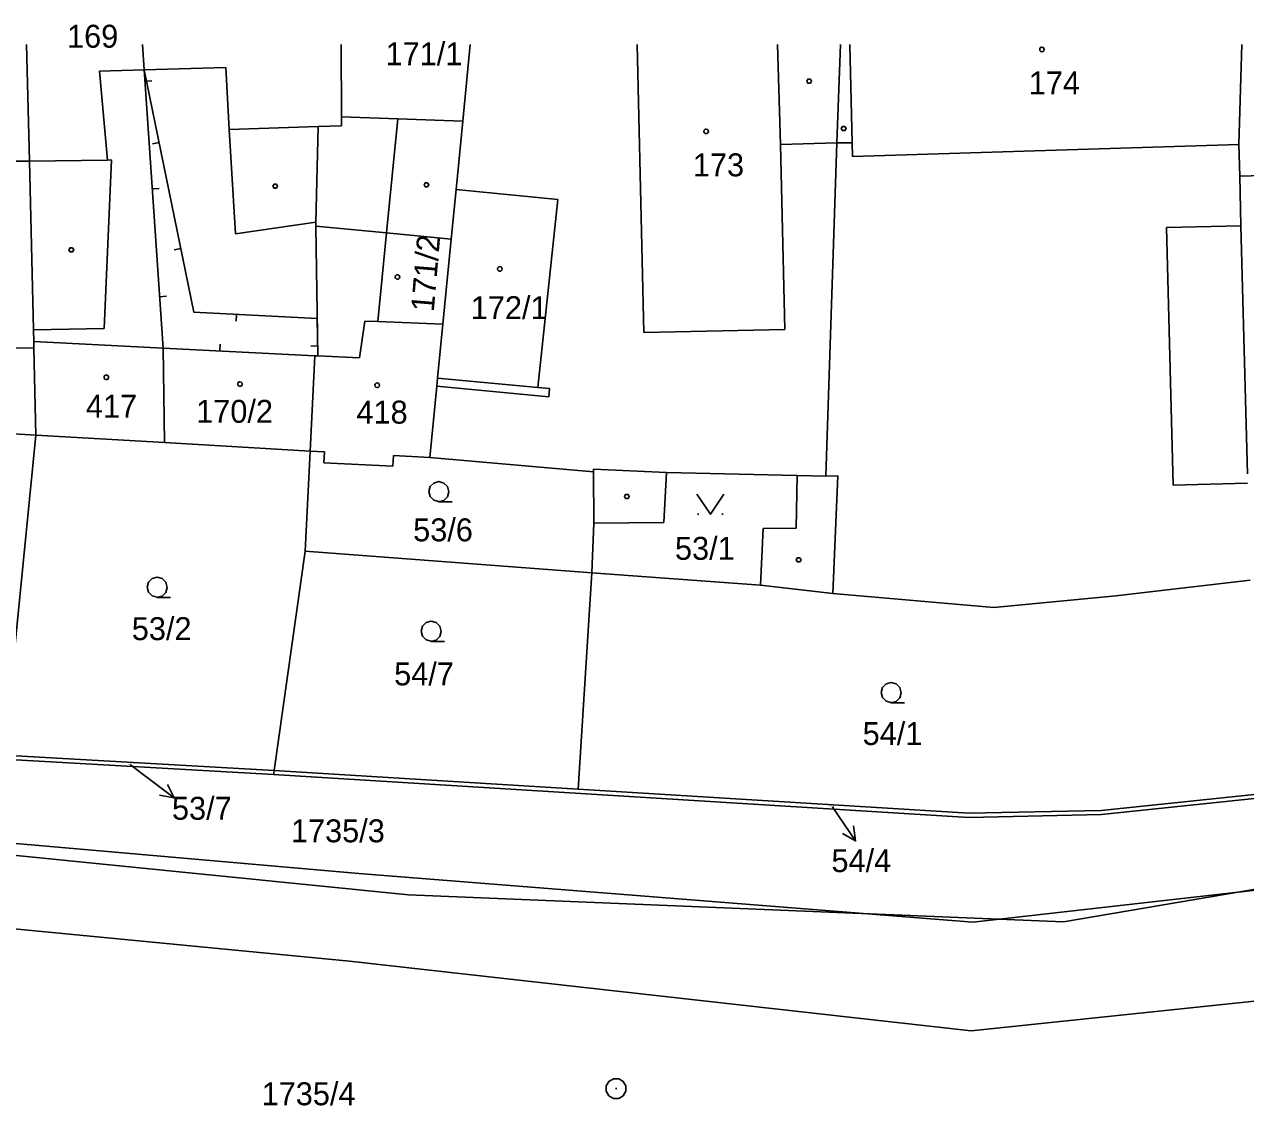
# Model space of a CAD drawing. Extents: x -777309 to -774195, y -1144706 to -1143600.
# Drawn here: x -774889 to -774798.5, y -1144278.6 to -1144198.5 of the extents above; entities that cross this region are included whole.
import ezdxf

# ---------------------------------------------------------------- set-up
doc = ezdxf.new("R2010")
doc.units = 0
for name, color, linetype in [('1', 7, 'Continuous'), ('11', 7, 'Continuous'), ('12', 7, 'Continuous'), ('13', 7, 'Continuous'), ('2', 7, 'Continuous'), ('3', 7, 'Continuous'), ('4', 7, 'Continuous'), ('5', 7, 'Continuous'), ('7', 7, 'Continuous'), ('8', 7, 'Continuous')]:
    doc.layers.add(name, color=color, linetype=linetype)

msp = doc.modelspace()

# ---------------------------------------------------------------- linework, layer by layer
at = {"layer": '1'}
for p, q in [((-774888.59, -1144208.64), (-774888.8, -1144200)), ((-774880.207, -1144200), (-774880.08, -1144201.87)), ((-774865.48, -1144205.35), (-774865.502, -1144200)), ((-774855.935, -1144200), (-774856.49, -1144205.68)), ((-774843.569, -1144200), (-774843.07, -1144221.34)), ((-774828.514, -1144200), (-774828.78, -1144207.29)), ((-774799, -1144207.4), (-774798.795, -1144200)), ((-774880.08, -1144201.87), (-774878.67, -1144222.48)), ((-774865.47, -1144206.03), (-774865.48, -1144205.35)), ((-774867.37, -1144213.16), (-774867.21, -1144206.06)), ((-774867.21, -1144206.06), (-774865.47, -1144206.03)), ((-774856.99, -1144210.73), (-774856.49, -1144205.68)), ((-774832.95, -1144207.39), (-774828.78, -1144207.29)), ((-774832.63, -1144221.1), (-774832.95, -1144207.39)), ((-774828.78, -1144207.29), (-774829.59, -1144231.98)), ((-774798.94, -1144209.74), (-774799, -1144207.4)), ((-774888.29, -1144221.14), (-774888.59, -1144208.64)), ((-774798.85, -1144213.42), (-774798.94, -1144209.74)), ((-774856.99, -1144210.73), (-774857.35, -1144214.42)), ((-774867.36, -1144213.44), (-774867.37, -1144213.16)), ((-774862.13, -1144213.95), (-774867.36, -1144213.44)), ((-774867.23, -1144223.06), (-774867.36, -1144213.44)), ((-774798.37, -1144231.8), (-774798.85, -1144213.42)), ((-774862.13, -1144213.95), (-774857.35, -1144214.42)), ((-774857.35, -1144214.42), (-774857.97, -1144220.7)), ((-774863.74, -1144220.49), (-774864.15, -1144223.21)), ((-774862.77, -1144220.52), (-774863.74, -1144220.49)), ((-774862.77, -1144220.52), (-774857.97, -1144220.7)), ((-774857.97, -1144220.7), (-774858.36, -1144224.71)), ((-774888.27, -1144221.99), (-774888.29, -1144221.14)), ((-774843.07, -1144221.34), (-774832.63, -1144221.1)), ((-774888.26, -1144222.49), (-774888.27, -1144221.99)), ((-774878.67, -1144222.48), (-774888.27, -1144221.99)), ((-774888.1, -1144228.93), (-774888.26, -1144222.49)), ((-774867.45, -1144223.05), (-774878.67, -1144222.48)), ((-774878.67, -1144222.48), (-774878.59, -1144229.48)), ((-774867.78, -1144230.11), (-774867.45, -1144223.05)), ((-774867.45, -1144223.05), (-774867.23, -1144223.06)), ((-774864.15, -1144223.21), (-774867.23, -1144223.06)), ((-774858.42, -1144225.31), (-774858.94, -1144230.59)), ((-774858.36, -1144224.71), (-774858.42, -1144225.31)), ((-774888.1, -1144228.93), (-774896.67, -1144228.43)), ((-774890.45, -1144252.65), (-774888.1, -1144228.93)), ((-774878.59, -1144229.48), (-774888.1, -1144228.93)), ((-774867.78, -1144230.11), (-774878.59, -1144229.48)), ((-774868.17, -1144237.53), (-774867.78, -1144230.11)), ((-774866.73, -1144230.17), (-774867.78, -1144230.11)), ((-774866.78, -1144230.99), (-774866.73, -1144230.17)), ((-774861.66, -1144231.24), (-774866.78, -1144230.99)), ((-774861.61, -1144230.45), (-774861.66, -1144231.24)), ((-774858.94, -1144230.59), (-774861.61, -1144230.45)), ((-774858.94, -1144230.59), (-774846.81, -1144231.65)), ((-774846.81, -1144231.65), (-774846.78, -1144235.45)), ((-774841.6, -1144235.41), (-774841.4, -1144231.69)), ((-774841.4, -1144231.69), (-774831.71, -1144231.93)), ((-774831.71, -1144231.93), (-774831.8, -1144235.82)), ((-774829.59, -1144231.98), (-774828.72, -1144231.96)), ((-774828.72, -1144231.96), (-774829.09, -1144240.66)), ((-774846.94, -1144239.14), (-774846.78, -1144235.45)), ((-774846.78, -1144235.45), (-774841.6, -1144235.41)), ((-774834.25, -1144235.84), (-774834.43, -1144240.06)), ((-774831.8, -1144235.82), (-774834.25, -1144235.84)), ((-774868.17, -1144237.53), (-774870.47, -1144253.78)), ((-774846.94, -1144239.14), (-774868.17, -1144237.53)), ((-774846.94, -1144239.14), (-774847.93, -1144255.17)), ((-774834.43, -1144240.06), (-774846.94, -1144239.14)), ((-774808.13, -1144240.85), (-774798.17, -1144239.67)), ((-774829.09, -1144240.66), (-774834.43, -1144240.06)), ((-774829.09, -1144240.66), (-774817.16, -1144241.7)), ((-774817.16, -1144241.7), (-774808.13, -1144240.85)), ((-774890.45, -1144252.65), (-774870.47, -1144253.78)), ((-774890.48, -1144252.95), (-774870.51, -1144254.08)), ((-774870.47, -1144253.78), (-774870.51, -1144254.08)), ((-774819, -1144257.25), (-774870.51, -1144254.08)), ((-774870.47, -1144253.78), (-774847.93, -1144255.17)), ((-774847.93, -1144255.17), (-774819, -1144256.95)), ((-774809.2, -1144256.75), (-774790.9, -1144254.82)), ((-774790.85, -1144255.12), (-774809.17, -1144257.05)), ((-774819, -1144256.95), (-774809.2, -1144256.75)), ((-774809.17, -1144257.05), (-774819, -1144257.25)), ((-774864.19, -1144261.41), (-774902.17, -1144258.08)), ((-774818.72, -1144265.01), (-774773.33, -1144259.89)), ((-774864.19, -1144261.41), (-774818.72, -1144265.01)), ((-774864.87, -1144267.9), (-774902.82, -1144264.25)), ((-774818.84, -1144273.07), (-774864.87, -1144267.9)), ((-774782.45, -1144269.27), (-774818.84, -1144273.07))]:
    msp.add_line(p, q, dxfattribs=at)
at = {"layer": '11'}
msp.add_lwpolyline([(-774645.079, -1144200), (-774645.5, -1144200.5), (-774681.5, -1144228), (-774709.5, -1144242), (-774744.5, -1144253.5), (-774812, -1144265), (-774860.5, -1144263), (-774969.04, -1144252.1), (-774980.31, -1144239.8), (-774996.3, -1144228.96), (-775000, -1144226.45), (-775000, -1144224.76), (-775020.31, -1144224.68)], dxfattribs=at)
at = {"layer": '12'}
for p, q in [((-774888.59, -1144208.64), (-774888.8, -1144200)), ((-774888.59, -1144208.64), (-774888.8, -1144200)), ((-774880.207, -1144200), (-774880.08, -1144201.87)), ((-774880.207, -1144200), (-774880.08, -1144201.87)), ((-774865.48, -1144205.35), (-774865.502, -1144200)), ((-774865.48, -1144205.35), (-774865.502, -1144200)), ((-774855.935, -1144200), (-774856.49, -1144205.68)), ((-774843.569, -1144200), (-774843.07, -1144221.34)), ((-774832.95, -1144207.39), (-774833.173, -1144200)), ((-774827.65, -1144207.27), (-774827.824, -1144200)), ((-774799, -1144207.4), (-774798.795, -1144200)), ((-774799, -1144207.4), (-774798.795, -1144200)), ((-774883.39, -1144201.96), (-774880.08, -1144201.87)), ((-774882.8, -1144208.55), (-774883.39, -1144201.96)), ((-774880.08, -1144201.87), (-774874.04, -1144201.7)), ((-774874.04, -1144201.7), (-774873.78, -1144206.3)), ((-774865.47, -1144206.03), (-774865.48, -1144205.35)), ((-774865.48, -1144205.35), (-774861.3, -1144205.5)), ((-774861.3, -1144205.5), (-774856.49, -1144205.68)), ((-774873.78, -1144206.3), (-774867.21, -1144206.06)), ((-774867.21, -1144206.06), (-774865.47, -1144206.03)), ((-774832.63, -1144221.1), (-774832.95, -1144207.39)), ((-774827.65, -1144207.27), (-774827.63, -1144208.28)), ((-774827.63, -1144208.28), (-774799, -1144207.4)), ((-774798.94, -1144209.74), (-774799, -1144207.4)), ((-774892.65, -1144208.65), (-774888.59, -1144208.64)), ((-774888.59, -1144208.64), (-774882.8, -1144208.55)), ((-774758.75, -1144208.58), (-774798.94, -1144209.74)), ((-774856.99, -1144210.73), (-774857.35, -1144214.42)), ((-774856.99, -1144210.73), (-774849.45, -1144211.47)), ((-774849.45, -1144211.47), (-774850.94, -1144225.41)), ((-774862.13, -1144213.95), (-774862.77, -1144220.52)), ((-774862.13, -1144213.95), (-774857.35, -1144214.42)), ((-774857.35, -1144214.42), (-774857.97, -1144220.7)), ((-774857.35, -1144214.42), (-774857.97, -1144220.7)), ((-774863.74, -1144220.49), (-774864.15, -1144223.21)), ((-774862.77, -1144220.52), (-774863.74, -1144220.49)), ((-774862.77, -1144220.52), (-774857.97, -1144220.7)), ((-774862.77, -1144220.52), (-774857.97, -1144220.7)), ((-774857.97, -1144220.7), (-774858.36, -1144224.71)), ((-774857.97, -1144220.7), (-774858.36, -1144224.71)), ((-774843.07, -1144221.34), (-774832.63, -1144221.1)), ((-774888.26, -1144222.49), (-774888.27, -1144221.99)), ((-774878.67, -1144222.48), (-774888.27, -1144221.99)), ((-774888.1, -1144228.93), (-774888.26, -1144222.49)), ((-774878.67, -1144222.48), (-774878.59, -1144229.48)), ((-774867.45, -1144223.05), (-774878.67, -1144222.48)), ((-774878.67, -1144222.48), (-774878.59, -1144229.48)), ((-774867.78, -1144230.11), (-774867.45, -1144223.05)), ((-774867.78, -1144230.11), (-774867.45, -1144223.05)), ((-774867.45, -1144223.05), (-774867.23, -1144223.06)), ((-774864.15, -1144223.21), (-774867.23, -1144223.06)), ((-774858.42, -1144225.31), (-774858.94, -1144230.59)), ((-774858.36, -1144224.71), (-774858.42, -1144225.31)), ((-774858.36, -1144224.71), (-774850.94, -1144225.41)), ((-774878.59, -1144229.48), (-774888.1, -1144228.93)), ((-774867.78, -1144230.11), (-774878.59, -1144229.48)), ((-774866.73, -1144230.17), (-774867.78, -1144230.11)), ((-774866.78, -1144230.99), (-774866.73, -1144230.17)), ((-774861.66, -1144231.24), (-774866.78, -1144230.99)), ((-774861.61, -1144230.45), (-774861.66, -1144231.24)), ((-774858.94, -1144230.59), (-774861.61, -1144230.45))]:
    msp.add_line(p, q, dxfattribs=at)
at = {"layer": '13'}
for p, q in [((-774880.022, -1144202.716), (-774879.523, -1144202.682)), ((-774878.976, -1144207.258), (-774879.466, -1144207.358)), ((-774879.476, -1144210.698), (-774878.977, -1144210.664)), ((-774877.37, -1144215.095), (-774877.86, -1144215.195)), ((-774878.93, -1144218.679), (-774878.431, -1144218.645)), ((-774873.237, -1144219.993), (-774873.263, -1144220.492)), ((-774874.485, -1144222.693), (-774874.46, -1144222.193)), ((-774867.241, -1144222.325), (-774867.741, -1144222.332))]:
    msp.add_line(p, q, dxfattribs=at)
msp.add_lwpolyline([(-774880.08, -1144201.87), (-774876.4, -1144219.83), (-774867.27, -1144220.3), (-774867.23, -1144223.06), (-774867.45, -1144223.05), (-774878.67, -1144222.48)], close=True, dxfattribs=at)
at = {"layer": '3'}
for p, q in [((-774839.1, -1144234.8), (-774839, -1144234.8)), ((-774837.3, -1144234.8), (-774837.2, -1144234.8))]:
    msp.add_line(p, q, dxfattribs=at)
for points in [[(-774858.25, -1144233.86), (-774858.63, -1144233.76), (-774858.9, -1144233.49), (-774859, -1144233.12), (-774858.9, -1144232.75), (-774858.63, -1144232.48), (-774858.26, -1144232.38), (-774857.89, -1144232.48), (-774857.62, -1144232.75), (-774857.52, -1144233.13), (-774857.62, -1144233.51), (-774857.89, -1144233.78), (-774858.27, -1144233.88), (-774857.27, -1144233.88)], [(-774839.15, -1144233.3), (-774838.15, -1144234.8), (-774837.15, -1144233.3)], [(-774879.11, -1144240.94), (-774879.49, -1144240.84), (-774879.76, -1144240.57), (-774879.86, -1144240.2), (-774879.76, -1144239.83), (-774879.49, -1144239.56), (-774879.12, -1144239.46), (-774878.75, -1144239.56), (-774878.48, -1144239.83), (-774878.38, -1144240.21), (-774878.48, -1144240.59), (-774878.75, -1144240.86), (-774879.13, -1144240.96), (-774878.13, -1144240.96)], [(-774858.82, -1144244.2), (-774859.2, -1144244.1), (-774859.47, -1144243.83), (-774859.57, -1144243.46), (-774859.47, -1144243.09), (-774859.2, -1144242.82), (-774858.83, -1144242.72), (-774858.46, -1144242.82), (-774858.19, -1144243.09), (-774858.09, -1144243.47), (-774858.19, -1144243.85), (-774858.46, -1144244.12), (-774858.84, -1144244.22), (-774857.84, -1144244.22)], [(-774824.76, -1144248.75), (-774825.14, -1144248.65), (-774825.41, -1144248.38), (-774825.51, -1144248.01), (-774825.41, -1144247.64), (-774825.14, -1144247.37), (-774824.77, -1144247.27), (-774824.4, -1144247.37), (-774824.13, -1144247.64), (-774824.03, -1144248.02), (-774824.13, -1144248.4), (-774824.4, -1144248.67), (-774824.78, -1144248.77), (-774823.78, -1144248.77)]]:
    msp.add_lwpolyline(points, dxfattribs=at)
at = {"layer": '4'}
for p, q in [((-774832.95, -1144207.39), (-774833.173, -1144200)), ((-774827.65, -1144207.27), (-774827.824, -1144200)), ((-774883.39, -1144201.96), (-774880.08, -1144201.87)), ((-774882.8, -1144208.55), (-774883.39, -1144201.96)), ((-774880.08, -1144201.87), (-774874.04, -1144201.7)), ((-774874.04, -1144201.7), (-774873.78, -1144206.3)), ((-774865.48, -1144205.35), (-774861.3, -1144205.5)), ((-774861.3, -1144205.5), (-774862.13, -1144213.95)), ((-774861.3, -1144205.5), (-774856.49, -1144205.68)), ((-774873.78, -1144206.3), (-774867.21, -1144206.06)), ((-774873.78, -1144206.3), (-774873.33, -1144214.02)), ((-774828.78, -1144207.29), (-774827.65, -1144207.27)), ((-774827.65, -1144207.27), (-774827.63, -1144208.28)), ((-774827.63, -1144208.28), (-774799, -1144207.4)), ((-774892.65, -1144208.65), (-774888.59, -1144208.64)), ((-774888.59, -1144208.64), (-774882.8, -1144208.55)), ((-774883.06, -1144221.03), (-774882.5, -1144208.54)), ((-774882.5, -1144208.54), (-774882.8, -1144208.55)), ((-774758.75, -1144208.58), (-774798.94, -1144209.74)), ((-774856.99, -1144210.73), (-774849.45, -1144211.47)), ((-774849.45, -1144211.47), (-774850.94, -1144225.41)), ((-774873.33, -1144214.02), (-774867.37, -1144213.16)), ((-774798.85, -1144213.42), (-774804.37, -1144213.56)), ((-774804.37, -1144213.56), (-774803.88, -1144232.63)), ((-774862.13, -1144213.95), (-774862.77, -1144220.52)), ((-774888.29, -1144221.14), (-774883.06, -1144221.03)), ((-774892.63, -1144222.47), (-774888.26, -1144222.49)), ((-774850.12, -1144226.09), (-774858.42, -1144225.31)), ((-774858.36, -1144224.71), (-774850.94, -1144225.41)), ((-774850.94, -1144225.41), (-774850.06, -1144225.49)), ((-774850.06, -1144225.49), (-774850.12, -1144226.09)), ((-774846.81, -1144231.65), (-774846.81, -1144231.45)), ((-774846.81, -1144231.45), (-774841.4, -1144231.69)), ((-774831.71, -1144231.93), (-774829.59, -1144231.98)), ((-774803.88, -1144232.63), (-774798.36, -1144232.49))]:
    msp.add_line(p, q, dxfattribs=at)
at = {"layer": '5'}
for points in [[(-774813.59, -1144200.19), (-774813.49, -1144200.21), (-774813.44, -1144200.3), (-774813.42, -1144200.36), (-774813.44, -1144200.45), (-774813.52, -1144200.52), (-774813.59, -1144200.53), (-774813.68, -1144200.5), (-774813.74, -1144200.44), (-774813.76, -1144200.36), (-774813.74, -1144200.27), (-774813.66, -1144200.2)], [(-774830.74, -1144202.56), (-774830.65, -1144202.71), (-774830.74, -1144202.86), (-774830.92, -1144202.86), (-774831.01, -1144202.71), (-774830.92, -1144202.56)], [(-774838.47, -1144206.26), (-774838.37, -1144206.28), (-774838.32, -1144206.37), (-774838.3, -1144206.43), (-774838.32, -1144206.52), (-774838.4, -1144206.59), (-774838.47, -1144206.6), (-774838.56, -1144206.57), (-774838.62, -1144206.51), (-774838.64, -1144206.43), (-774838.62, -1144206.34), (-774838.54, -1144206.27)], [(-774828.19, -1144206.07), (-774828.1, -1144206.22), (-774828.19, -1144206.37), (-774828.37, -1144206.37), (-774828.46, -1144206.22), (-774828.37, -1144206.07)], [(-774870.29, -1144210.34), (-774870.2, -1144210.49), (-774870.29, -1144210.64), (-774870.47, -1144210.64), (-774870.56, -1144210.49), (-774870.47, -1144210.34)], [(-774859.09, -1144210.23), (-774859, -1144210.38), (-774859.09, -1144210.53), (-774859.27, -1144210.53), (-774859.36, -1144210.38), (-774859.27, -1144210.23)], [(-774885.39, -1144215.06), (-774885.3, -1144215.21), (-774885.39, -1144215.36), (-774885.57, -1144215.36), (-774885.66, -1144215.21), (-774885.57, -1144215.06)], [(-774853.74, -1144216.45), (-774853.64, -1144216.47), (-774853.59, -1144216.56), (-774853.57, -1144216.62), (-774853.59, -1144216.71), (-774853.67, -1144216.78), (-774853.74, -1144216.79), (-774853.83, -1144216.76), (-774853.89, -1144216.7), (-774853.91, -1144216.62), (-774853.89, -1144216.53), (-774853.81, -1144216.46)], [(-774861.33, -1144217.05), (-774861.23, -1144217.07), (-774861.18, -1144217.16), (-774861.16, -1144217.22), (-774861.18, -1144217.31), (-774861.26, -1144217.38), (-774861.33, -1144217.39), (-774861.42, -1144217.36), (-774861.48, -1144217.3), (-774861.5, -1144217.22), (-774861.48, -1144217.13), (-774861.4, -1144217.06)], [(-774882.89, -1144224.48), (-774882.79, -1144224.5), (-774882.74, -1144224.59), (-774882.72, -1144224.65), (-774882.74, -1144224.74), (-774882.82, -1144224.81), (-774882.89, -1144224.82), (-774882.98, -1144224.79), (-774883.04, -1144224.73), (-774883.06, -1144224.65), (-774883.04, -1144224.56), (-774882.96, -1144224.49)], [(-774872.99, -1144224.98), (-774872.89, -1144225), (-774872.84, -1144225.09), (-774872.82, -1144225.15), (-774872.84, -1144225.24), (-774872.92, -1144225.31), (-774872.99, -1144225.32), (-774873.08, -1144225.29), (-774873.14, -1144225.23), (-774873.16, -1144225.15), (-774873.14, -1144225.06), (-774873.06, -1144224.99)], [(-774862.83, -1144225.07), (-774862.73, -1144225.09), (-774862.68, -1144225.18), (-774862.66, -1144225.24), (-774862.68, -1144225.33), (-774862.76, -1144225.4), (-774862.83, -1144225.41), (-774862.92, -1144225.38), (-774862.98, -1144225.32), (-774863, -1144225.24), (-774862.98, -1144225.15), (-774862.9, -1144225.08)], [(-774844.25, -1144233.32), (-774844.16, -1144233.47), (-774844.25, -1144233.62), (-774844.43, -1144233.62), (-774844.52, -1144233.47), (-774844.43, -1144233.32)], [(-774831.52, -1144238.02), (-774831.43, -1144238.17), (-774831.52, -1144238.32), (-774831.7, -1144238.32), (-774831.79, -1144238.17), (-774831.7, -1144238.02)]]:
    msp.add_lwpolyline(points, close=True, dxfattribs=at)
at = {"layer": '7'}
for p, q in [((-774881.09, -1144253.37), (-774880.25, -1144254)), ((-774877.859, -1144255.812), (-774880.25, -1144254)), ((-774829.11, -1144256.48), (-774829.09, -1144256.52)), ((-774827.398, -1144258.997), (-774829.09, -1144256.52))]:
    msp.add_line(p, q, dxfattribs=at)
for points in [[(-774878.354, -1144254.809), (-774877.859, -1144255.812), (-774878.958, -1144255.606)], [(-774827.549, -1144257.889), (-774827.398, -1144258.997), (-774828.375, -1144258.453)]]:
    msp.add_lwpolyline(points, dxfattribs=at)
at = {"layer": '8'}
msp.add_line((-774845.18, -1144277.34), (-774845.08, -1144277.34), dxfattribs=at)
msp.add_lwpolyline([(-774844.94, -1144276.62), (-774844.6, -1144276.81), (-774844.41, -1144277.15), (-774844.41, -1144277.54), (-774844.6, -1144277.88), (-774844.94, -1144278.07), (-774845.33, -1144278.07), (-774845.67, -1144277.88), (-774845.86, -1144277.54), (-774845.86, -1144277.15), (-774845.67, -1144276.81), (-774845.33, -1144276.62)], close=True, dxfattribs=at)

# ---------------------------------------------------------------- texts
at = {"layer": '2'}
for s, height, p in [('169', 1.7, (-774885.797, -1144200.23)), ('171/1', 1.7, (-774862.207, -1144201.53)), ('174', 1.7, (-774814.567, -1144203.69)), ('173', 1.7, (-774839.447, -1144209.76)), ('172/1', 1.7, (-774855.897, -1144220.34)), ('417', 1.7, (-774884.403, -1144227.64)), ('170/2', 1.7, (-774876.235, -1144228.02)), ('418', 1.7, (-774864.363, -1144228.08)), ('53/6', 1.7, (-774860.163, -1144236.8)), ('53/1', 1.7, (-774840.773, -1144238.17)), ('53/2', 1.7, (-774881.003, -1144244.12)), ('54/7', 1.7, (-774861.571, -1144247.47)), ('54/1', 1.7, (-774826.873, -1144251.89)), ('53/7', 0.1, (-774881.257, -1144253.37)), ('54/4', 0.1, (-774829.274, -1144256.48)), ('1735/3', 1.7, (-774869.217, -1144259.1)), ('1735/4', 1.7, (-774871.387, -1144278.58))]:
    msp.add_text(s, height=height, dxfattribs=at).set_placement(p)
msp.add_text('171/2', height=1.7, rotation=85.14153, dxfattribs=at).set_placement((-774858.637, -1144219.839))
at = {"layer": '7'}
for s, p in [('53/7', (-774878.028, -1144257.43)), ('54/4', (-774829.181, -1144261.31))]:
    msp.add_text(s, height=1.7, dxfattribs=at).set_placement(p)

doc.saveas('drawing.dxf')
